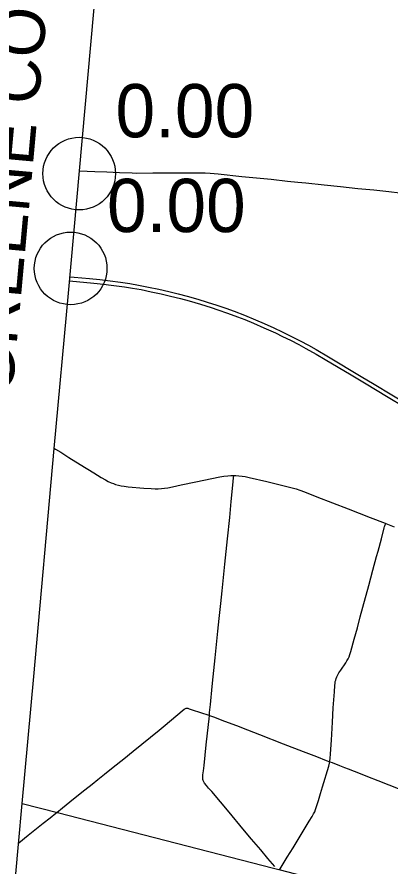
# Model space of a CAD drawing. Extents: x 1597222 to 1925846, y 496284 to 911751.
# Drawn here: x 1640665 to 1648365, y 590130 to 607664 of the extents above; entities that cross this region are included whole.
import ezdxf

# ---------------------------------------------------------------- set-up
doc = ezdxf.new("R2010")
doc.units = 0
for name, color, linetype in [('Default', 7, 'Continuous'), ('GM_X_Adjacent_County_Text', 7, 'Continuous'), ('GM_X_County', 7, 'Continuous'), ('GM_X_County_Road', 7, 'Continuous'), ('GM_X_State_Route', 7, 'Continuous'), ('GM_X_Township', 7, 'Continuous'), ('GM_X_Township_Road', 7, 'Continuous'), ('GM_X_US_Route', 7, 'Continuous')]:
    doc.layers.add(name, color=color, linetype=linetype)

msp = doc.modelspace()

# ---------------------------------------------------------------- linework, layer by layer
at = {"layer": 'Default'}
for centre in [(1641949, 604429), (1641949, 604429), (1641773, 602472), (1641773, 602472)]:
    msp.add_circle(centre, 750, dxfattribs=at)
at = {"layer": 'GM_X_County'}
msp.add_lwpolyline([(1640197, 585063), (1640696, 590579), (1640772, 591419), (1641010, 594042), (1641435, 598750), (1641726, 601963), (1641954, 604485), (1642314, 608472)], dxfattribs=at)
at = {"layer": 'GM_X_County_Road'}
for points in [[(1641439, 598752), (1641457, 598741), (1641569, 598675), (1641736, 598570), (1641972, 598422), (1642250, 598247), (1642404, 598153), (1642489, 598103), (1642548, 598073), (1642608, 598046), (1642654, 598028), (1642701, 598012), (1642764, 597995), (1642813, 597985), (1642878, 597974), (1642959, 597964), (1643286, 597936), (1643434, 597925), (1643516, 597922), (1643582, 597922), (1643648, 597926), (1643713, 597933), (1643778, 597943), (1643875, 597961), (1644052, 597999), (1644357, 598063), (1644855, 598165), (1644936, 598179), (1645017, 598189), (1645082, 598194), (1645131, 598196), (1645142, 598195)], [(1645142, 598195), (1645180, 598194), (1645245, 598190), (1645310, 598182), (1645375, 598172), (1645455, 598155), (1645822, 598068), (1646205, 597977), (1646348, 597940), (1646427, 597917), (1646505, 597892), (1646597, 597858), (1646857, 597756), (1647499, 597507), (1647959, 597329), (1648264, 597210), (1648280, 597204)], [(1647121, 592283), (1647125, 592303), (1647131, 592351), (1647138, 592449), (1647154, 592728), (1647177, 593104), (1647195, 593399), (1647217, 593726), (1647226, 593857), (1647231, 593906), (1647236, 593939), (1647244, 593971), (1647253, 594003), (1647265, 594034), (1647287, 594078), (1647311, 594122), (1647347, 594177), (1647450, 594325), (1647477, 594366), (1647500, 594409), (1647520, 594453), (1647537, 594499), (1647556, 594562), (1647627, 594814), (1647691, 595052), (1647751, 595274), (1647807, 595479), (1647927, 595923), (1648013, 596239), (1648089, 596524), (1648119, 596635), (1648187, 596889), (1648245, 597111), (1648254, 597143), (1648260, 597158), (1648266, 597174), (1648280, 597204)], [(1648280, 597204), (1648448, 597138), (1648451, 597137)], [(1646086, 590053), (1646100, 590073), (1646245, 590311), (1646363, 590508), (1646551, 590816), (1646697, 591054), (1646756, 591151), (1646788, 591208), (1646810, 591252), (1646830, 591297), (1646851, 591359), (1646889, 591484), (1646931, 591626), (1646972, 591767), (1647099, 592192), (1647115, 592255), (1647121, 592283)]]:
    msp.add_lwpolyline(points, dxfattribs=at)
at = {"layer": 'GM_X_State_Route'}
msp.add_lwpolyline([(1641958, 604488), (1642273, 604476), (1642519, 604466), (1642782, 604455), (1643044, 604443), (1643142, 604442), (1643470, 604444), (1644044, 604448), (1644274, 604448), (1644455, 604448), (1644553, 604445), (1644652, 604438), (1644815, 604422), (1645305, 604373), (1645909, 604312), (1646252, 604277), (1646464, 604254), (1646627, 604237), (1647003, 604200), (1647345, 604163), (1647704, 604125), (1648031, 604092), (1648341, 604060), (1648569, 604036)], dxfattribs=at)
at = {"layer": 'GM_X_Township'}
msp.add_lwpolyline([(1640772, 591419), (1641501, 591232), (1645959, 590087), (1646099, 590051), (1651332, 588679), (1652031, 588630), (1654972, 588478), (1658610, 588362), (1660153, 588344), (1660296, 588340), (1662371, 588281), (1662472, 588280), (1663570, 588267), (1665903, 588241), (1668490, 588131), (1673343, 587846), (1673034, 583935), (1673000, 583850), (1672955, 583266), (1672719, 580558), (1678923, 579915)], dxfattribs=at)
at = {"layer": 'GM_X_Township_Road'}
for points in [[(1644636, 593241), (1644642, 593299), (1644658, 593463), (1644697, 593839), (1644718, 594035), (1644758, 594426), (1644785, 594704), (1644814, 594981), (1644841, 595242), (1644873, 595552), (1644902, 595813), (1644959, 596367), (1644984, 596628), (1645010, 596889), (1645056, 597330), (1645087, 597656), (1645123, 597998), (1645137, 598145), (1645142, 598195)], [(1641485, 591237), (1641602, 591332), (1641833, 591517), (1642063, 591701), (1642218, 591823), (1642332, 591917), (1642473, 592030), (1642652, 592173), (1642871, 592347), (1643062, 592501), (1643599, 592933), (1643726, 593037), (1644075, 593336), (1644113, 593367), (1644127, 593376), (1644141, 593383), (1644157, 593387), (1644174, 593389), (1644190, 593387), (1644222, 593379), (1644284, 593358), (1644455, 593300), (1644626, 593244), (1644636, 593241)], [(1645986, 590117), (1645845, 590286), (1645697, 590462), (1645508, 590686), (1645328, 590901), (1645044, 591241), (1644684, 591666), (1644620, 591741), (1644579, 591792), (1644537, 591842), (1644527, 591856), (1644519, 591870), (1644512, 591884), (1644506, 591899), (1644503, 591915), (1644501, 591931), (1644500, 591964), (1644504, 592013), (1644513, 592095), (1644526, 592209), (1644571, 592633), (1644597, 592877), (1644629, 593171), (1644636, 593241)], [(1644636, 593241), (1644719, 593212), (1644949, 593124), (1645194, 593029), (1645423, 592940), (1645668, 592845), (1646158, 592656), (1646572, 592497), (1646846, 592389), (1647045, 592312), (1647121, 592283)], [(1647121, 592283), (1647168, 592266), (1647321, 592208), (1647426, 592166)], [(1647426, 592166), (1647504, 592135), (1647627, 592088), (1647749, 592041), (1647901, 591980), (1648115, 591896), (1648344, 591805), (1648634, 591692)], [(1640702, 590609), (1640897, 590764), (1641208, 591012), (1641350, 591127), (1641464, 591219), (1641485, 591237)]]:
    msp.add_lwpolyline(points, dxfattribs=at)
at = {"layer": 'GM_X_US_Route'}
for points in [[(1641751, 602212), (1642252, 602170), (1642448, 602149), (1642611, 602129), (1642887, 602090), (1643049, 602064), (1643227, 602033), (1643436, 601991), (1643644, 601946), (1643836, 601902), (1644043, 601849), (1644217, 601802), (1644453, 601732), (1644673, 601664), (1644813, 601618), (1645014, 601548), (1645215, 601474), (1645368, 601415), (1645550, 601339), (1645760, 601248), (1646000, 601140), (1646148, 601069), (1646309, 600989), (1646484, 600898), (1646629, 600820), (1646843, 600699), (1647027, 600591), (1647562, 600271), (1647871, 600086), (1648294, 599833), (1648688, 599597)], [(1641758, 602297), (1641845, 602290), (1642165, 602261), (1642377, 602240), (1642589, 602215), (1642800, 602187), (1642995, 602157), (1643172, 602126), (1643382, 602085), (1643590, 602042), (1643798, 601995), (1643989, 601948), (1644179, 601898), (1644400, 601835), (1644588, 601777), (1644791, 601712), (1644977, 601648), (1645147, 601586), (1645361, 601503), (1645588, 601410), (1645769, 601333), (1645964, 601246), (1646142, 601162), (1646318, 601075), (1646508, 600978), (1646681, 600884), (1646838, 600796), (1647093, 600647), (1647769, 600243), (1648036, 600083), (1648768, 599644)]]:
    msp.add_lwpolyline(points, dxfattribs=at)

# ---------------------------------------------------------------- texts
at = {"layer": 'Default'}
for p in [(1642699, 605179), (1642699, 605179), (1642523, 603222), (1642523, 603222)]:
    msp.add_text('0.00', height=1100, dxfattribs=at).set_placement(p)
at = {"layer": 'GM_X_Adjacent_County_Text'}
msp.add_text('GREENE COUNTY', height=1000, rotation=84.8167, dxfattribs=at).set_placement((1640562, 599835))

doc.saveas('drawing.dxf')
